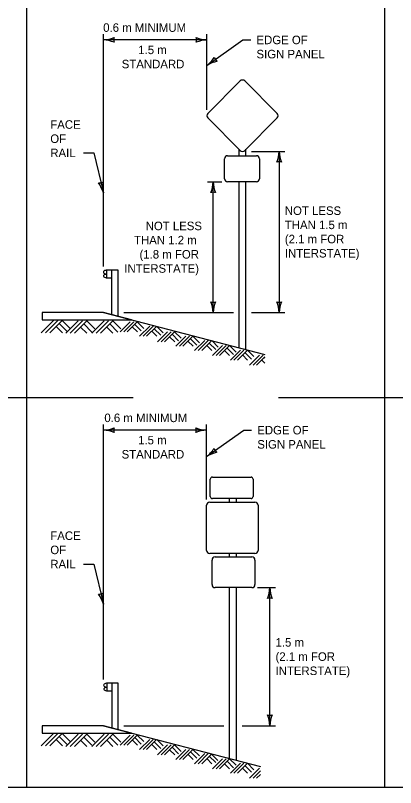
# Model space of a CAD drawing. Extents: x 49991.4 to 50021, y 49987.6 to 50011.4.
# Drawn here: x 50003.15 to 50005.83, y 49987.8 to 49993.24 of the extents above; entities that cross this region are included whole.
import ezdxf

# ---------------------------------------------------------------- set-up
doc = ezdxf.new("R2010")
doc.units = 0
for name, color, linetype in [('Level 1', 7, 'Continuous'), ('Level 2', 7, 'Continuous'), ('Level 3', 7, 'Continuous')]:
    doc.layers.add(name, color=color, linetype=linetype)

msp = doc.modelspace()

# ---------------------------------------------------------------- linework, layer by layer
at = {"layer": 'Level 1'}
for p, q in [((50004.5041, 49992.5484), (50004.7327, 49992.7772)), ((50004.7645, 49992.7772), (50004.9934, 49992.5484)), ((50004.7327, 49992.2877), (50004.5041, 49992.5166)), ((50004.9934, 49992.5166), (50004.7645, 49992.2877)), ((50004.7243, 49992.2506), (50004.7243, 49992.2961)), ((50004.7729, 49992.2506), (50004.7729, 49992.2961)), ((50004.622, 49992.0878), (50004.622, 49992.2291)), ((50004.6435, 49992.2506), (50004.8461, 49992.2506)), ((50004.8676, 49992.2291), (50004.8676, 49992.0878)), ((50004.8461, 49992.0663), (50004.6435, 49992.0663)), ((50004.7243, 49990.8966), (50004.7243, 49992.0663)), ((50004.7729, 49990.884), (50004.7729, 49992.0663)), ((50003.8289, 49991.4443), (50003.7883, 49991.4443)), ((50003.7901, 49991.4443), (50003.7901, 49991.391)), ((50003.8289, 49991.129), (50003.8289, 49991.4443)), ((50003.8718, 49991.4443), (50003.8289, 49991.4443)), ((50003.8718, 49991.1182), (50003.8718, 49991.4443)), ((50003.7883, 49991.391), (50003.8289, 49991.391)), ((50003.768, 49991.1452), (50003.336, 49991.1452)), ((50003.336, 49991.1452), (50003.336, 49991.0935)), ((50003.768, 49991.1452), (50003.336, 49991.1452)), ((50003.336, 49991.1452), (50003.336, 49991.0935)), ((50003.7682, 49991.1452), (50004.9063, 49990.8493)), ((50003.9668, 49991.0936), (50003.7682, 49991.1452)), ((50003.3298, 49991.0029), (50003.4171, 49991.0903)), ((50003.336, 49991.0935), (50003.9668, 49991.0935)), ((50003.336, 49991.0935), (50003.9668, 49991.0935)), ((50003.3605, 49991.0029), (50003.4478, 49991.0903)), ((50003.3909, 49991.0029), (50003.4782, 49991.0903)), ((50003.4782, 49991.0903), (50003.5351, 49991.0335)), ((50003.5026, 49990.9993), (50003.5899, 49991.0866)), ((50003.5333, 49990.9993), (50003.6206, 49991.0866)), ((50003.5637, 49990.9993), (50003.6511, 49991.0866)), ((50003.6511, 49991.0866), (50003.7079, 49991.0299)), ((50003.6861, 49990.9993), (50003.7734, 49991.0866)), ((50003.7168, 49990.9993), (50003.8041, 49991.0866)), ((50003.7472, 49990.9993), (50003.8346, 49991.0866)), ((50003.8346, 49991.0866), (50003.8914, 49991.0299)), ((50003.8863, 49991.0088), (50003.9571, 49991.0795)), ((50003.9112, 49991.0088), (50003.9819, 49991.0795)), ((50003.9358, 49991.0088), (50004.0065, 49991.0795)), ((50003.9665, 49991.0935), (50003.9665, 49991.0935)), ((50003.9668, 49991.0935), (50003.9668, 49991.0936)), ((50004.0065, 49991.0795), (50004.0526, 49991.0335)), ((50003.4351, 49991.047), (50003.4792, 49991.0029)), ((50003.4568, 49991.0687), (50003.5135, 49991.012)), ((50003.6079, 49991.0433), (50003.652, 49990.9993)), ((50003.6295, 49991.065), (50003.6862, 49991.0084)), ((50003.7914, 49991.0433), (50003.8355, 49990.9993)), ((50003.813, 49991.065), (50003.8697, 49991.0084)), ((50003.9716, 49991.0445), (50004.0075, 49991.0088)), ((50003.9891, 49991.0621), (50004.0352, 49991.0162)), ((50004.0238, 49990.9781), (50004.0945, 49991.0488)), ((50004.0486, 49990.9781), (50004.1193, 49991.0488)), ((50004.0732, 49990.9781), (50004.143, 49991.0477)), ((50004.1266, 49991.0314), (50004.1726, 49990.9855)), ((50004.1459, 49991.047), (50004.19, 49991.0028)), ((50004.109, 49991.0137), (50004.1449, 49990.9781)), ((50004.1495, 49990.9398), (50004.2202, 49991.0105)), ((50004.1744, 49990.9398), (50004.2451, 49991.0105)), ((50004.199, 49990.9398), (50004.2697, 49991.0105)), ((50004.2348, 49990.9755), (50004.2706, 49990.9398)), ((50004.2524, 49990.9931), (50004.2983, 49990.9472)), ((50004.2697, 49991.0105), (50004.3158, 49990.9645)), ((50004.2786, 49990.908), (50004.3493, 49990.9788)), ((50004.3036, 49990.908), (50004.3743, 49990.9788)), ((50004.3282, 49990.908), (50004.3989, 49990.9788)), ((50004.3989, 49990.9788), (50004.445, 49990.9327)), ((50004.3639, 49990.9436), (50004.3997, 49990.908)), ((50004.3814, 49990.9613), (50004.4274, 49990.9154)), ((50004.4114, 49990.8775), (50004.4821, 49990.9482)), ((50004.4362, 49990.8775), (50004.5071, 49990.9482)), ((50004.461, 49990.8775), (50004.5305, 49990.947)), ((50004.5142, 49990.9308), (50004.5602, 49990.8851)), ((50004.5338, 49990.9462), (50004.5778, 49990.9024)), ((50004.4967, 49990.9132), (50004.5324, 49990.8775)), ((50004.5369, 49990.8418), (50004.6076, 49990.9126)), ((50004.5619, 49990.8418), (50004.6326, 49990.9126)), ((50004.5864, 49990.8418), (50004.6571, 49990.9126)), ((50004.6222, 49990.8775), (50004.6579, 49990.8418)), ((50004.6396, 49990.8951), (50004.6857, 49990.8492)), ((50004.6571, 49990.9126), (50004.7033, 49990.8665)), ((50004.6631, 49990.8107), (50004.7339, 49990.8814)), ((50004.688, 49990.8107), (50004.7588, 49990.8814)), ((50004.7126, 49990.8107), (50004.7834, 49990.8813)), ((50004.766, 49990.864), (50004.812, 49990.8181)), ((50004.7837, 49990.8812), (50004.8295, 49990.8355)), ((50004.7485, 49990.8464), (50004.7842, 49990.8107)), ((50004.7985, 49990.7748), (50004.8692, 49990.8455)), ((50004.8235, 49990.7748), (50004.8942, 49990.8455)), ((50004.848, 49990.7748), (50004.9063, 49990.833)), ((50004.8839, 49990.8105), (50004.9063, 49990.7882)), ((50004.9013, 49990.8281), (50004.9063, 49990.8231)), ((50004.5214, 49989.8499), (50004.5214, 49989.9711)), ((50004.5364, 49989.9861), (50004.8085, 49989.9861)), ((50004.8235, 49989.9711), (50004.8235, 49989.8499)), ((50004.8085, 49989.8349), (50004.5364, 49989.8349)), ((50004.6569, 49989.8098), (50004.6569, 49989.8349)), ((50004.7055, 49989.8098), (50004.7055, 49989.8349)), ((50004.4955, 49989.4698), (50004.4955, 49989.7873)), ((50004.518, 49989.8098), (50004.8356, 49989.8098)), ((50004.8581, 49989.7873), (50004.8581, 49989.4698)), ((50004.8356, 49989.4473), (50004.518, 49989.4473)), ((50004.6569, 49989.4234), (50004.6569, 49989.4473)), ((50004.7055, 49989.4234), (50004.7055, 49989.4473)), ((50004.5342, 49989.229), (50004.5342, 49989.4019)), ((50004.5557, 49989.4234), (50004.8149, 49989.4234)), ((50004.8364, 49989.4019), (50004.8364, 49989.229)), ((50004.8149, 49989.2075), (50004.5557, 49989.2075)), ((50004.6569, 49988.0034), (50004.6569, 49989.2075)), ((50004.7056, 49987.9907), (50004.7056, 49989.2075)), ((50003.8302, 49988.5334), (50003.7896, 49988.5334)), ((50003.7914, 49988.5334), (50003.7914, 49988.4801)), ((50003.8302, 49988.2183), (50003.8302, 49988.5334)), ((50003.8731, 49988.5334), (50003.8302, 49988.5334)), ((50003.8731, 49988.2072), (50003.8731, 49988.5334)), ((50003.7896, 49988.4801), (50003.8302, 49988.4801)), ((50003.768, 49988.2345), (50003.336, 49988.2345)), ((50003.336, 49988.2345), (50003.336, 49988.1829)), ((50003.768, 49988.2345), (50003.336, 49988.2345)), ((50003.336, 49988.2345), (50003.336, 49988.1829)), ((50003.7682, 49988.2345), (50004.875, 49987.9467)), ((50003.9666, 49988.1829), (50003.7682, 49988.2345)), ((50003.3298, 49988.0923), (50003.4171, 49988.1796)), ((50003.336, 49988.1829), (50003.9667, 49988.1829)), ((50003.336, 49988.1829), (50003.9666, 49988.1829)), ((50003.3605, 49988.0923), (50003.4478, 49988.1796)), ((50003.3909, 49988.0923), (50003.4782, 49988.1796)), ((50003.4568, 49988.158), (50003.5135, 49988.1014)), ((50003.4782, 49988.1796), (50003.5351, 49988.1228)), ((50003.5026, 49988.0886), (50003.5899, 49988.176)), ((50003.5333, 49988.0886), (50003.6206, 49988.176)), ((50003.5637, 49988.0886), (50003.651, 49988.176)), ((50003.6295, 49988.1544), (50003.6862, 49988.0977)), ((50003.651, 49988.176), (50003.7079, 49988.1192)), ((50003.6861, 49988.0886), (50003.7734, 49988.176)), ((50003.7168, 49988.0886), (50003.8041, 49988.176)), ((50003.7472, 49988.0886), (50003.8345, 49988.176)), ((50003.813, 49988.1544), (50003.8697, 49988.0977)), ((50003.8345, 49988.176), (50003.8914, 49988.1192)), ((50003.8863, 49988.0981), (50003.957, 49988.1688)), ((50003.9112, 49988.0981), (50003.9819, 49988.1688)), ((50003.9358, 49988.0981), (50004.0065, 49988.1688)), ((50003.9665, 49988.1829), (50003.9665, 49988.1829)), ((50003.9891, 49988.1515), (50004.0351, 49988.1055)), ((50004.0065, 49988.1688), (50004.0526, 49988.1228)), ((50003.435, 49988.1363), (50003.4792, 49988.0923)), ((50003.6079, 49988.1327), (50003.652, 49988.0886)), ((50003.7914, 49988.1327), (50003.8355, 49988.0886)), ((50003.9716, 49988.1339), (50004.0075, 49988.0981)), ((50004.0237, 49988.0674), (50004.0944, 49988.1381)), ((50004.0486, 49988.0674), (50004.1193, 49988.1381)), ((50004.0732, 49988.0674), (50004.143, 49988.1371)), ((50004.109, 49988.1031), (50004.1449, 49988.0674)), ((50004.1266, 49988.1208), (50004.1725, 49988.0748)), ((50004.1458, 49988.1363), (50004.19, 49988.0922)), ((50004.1495, 49988.0291), (50004.2202, 49988.0998)), ((50004.1744, 49988.0291), (50004.2451, 49988.0998)), ((50004.199, 49988.0291), (50004.2697, 49988.0998)), ((50004.2697, 49988.0998), (50004.3158, 49988.0538)), ((50004.2348, 49988.0649), (50004.2705, 49988.0291)), ((50004.2524, 49988.0825), (50004.2983, 49988.0365)), ((50004.2785, 49987.9973), (50004.3493, 49988.0681)), ((50004.3035, 49987.9973), (50004.3742, 49988.0681)), ((50004.3282, 49987.9973), (50004.3989, 49988.0681)), ((50004.3639, 49988.033), (50004.3997, 49987.9973)), ((50004.3814, 49988.0507), (50004.4274, 49988.0047)), ((50004.3989, 49988.0681), (50004.4449, 49988.0221)), ((50004.4113, 49987.9669), (50004.4821, 49988.0376)), ((50004.4362, 49987.9669), (50004.507, 49988.0376)), ((50004.461, 49987.9669), (50004.5292, 49988.0351)), ((50004.5292, 49988.0351), (50004.5752, 49987.9892)), ((50004.4967, 49988.0025), (50004.5324, 49987.9669)), ((50004.5142, 49988.0201), (50004.5602, 49987.9744)), ((50004.5369, 49987.9311), (50004.6076, 49988.0019)), ((50004.5619, 49987.9311), (50004.6326, 49988.0019)), ((50004.5864, 49987.9311), (50004.6571, 49988.0019)), ((50004.6396, 49987.9845), (50004.6857, 49987.9385)), ((50004.6571, 49988.0019), (50004.7033, 49987.9558)), ((50004.6221, 49987.9669), (50004.6579, 49987.9311)), ((50004.6631, 49987.9), (50004.7338, 49987.9708)), ((50004.688, 49987.9), (50004.7588, 49987.9708)), ((50004.7126, 49987.9), (50004.7832, 49987.9706)), ((50004.7485, 49987.9357), (50004.7842, 49987.9)), ((50004.766, 49987.9533), (50004.8119, 49987.9074)), ((50004.7838, 49987.9704), (50004.8295, 49987.9248)), ((50004.7985, 49987.8641), (50004.8692, 49987.9349)), ((50004.8235, 49987.8641), (50004.875, 49987.9157)), ((50004.848, 49987.8641), (50004.875, 49987.8911))]:
    msp.add_line(p, q, dxfattribs=at)
msp.add_lwpolyline([(49999.3835, 49998.9992), (50016.7501, 49998.9992), (50016.7501, 49987.7988), (49999.3835, 49987.7988)], close=True, dxfattribs=at)
for centre, radius, start, end in [((50004.7486, 49992.7613), 0.0225, 45.011, 135.022), ((50004.52, 49992.5325), 0.0225, 135.022, 224.967), ((50004.9775, 49992.5325), 0.0225, 315, 45.011), ((50004.7486, 49992.3036), 0.0225, 224.967, 315), ((50004.6435, 49992.2291), 0.0215, 90, 180), ((50004.8461, 49992.2291), 0.0215, 0, 90), ((50004.6435, 49992.0878), 0.0215, 180, 270), ((50004.8461, 49992.0878), 0.0215, 270, 0), ((50004.5364, 49989.9711), 0.015, 90, 180), ((50004.8085, 49989.9711), 0.015, 0, 90), ((50004.5364, 49989.8499), 0.015, 180, 270), ((50004.8085, 49989.8499), 0.015, 270, 0), ((50004.518, 49989.7873), 0.0225, 90, 180), ((50004.8356, 49989.7873), 0.0225, 0, 90), ((50004.518, 49989.4698), 0.0225, 180, 270), ((50004.8356, 49989.4698), 0.0225, 270, 0), ((50004.5557, 49989.4019), 0.0215, 90, 180), ((50004.8149, 49989.4019), 0.0215, 0, 90), ((50004.5557, 49989.229), 0.0215, 180, 270), ((50004.8149, 49989.229), 0.0215, 270, 0)]:
    msp.add_arc(centre, radius, start, end, dxfattribs=at)
for points in [[(50003.7883, 49991.4443), (50003.7696, 49991.4337), (50003.7692, 49991.4267), (50003.7883, 49991.4176), (50003.789, 49991.4174), (50003.7692, 49991.4062), (50003.7696, 49991.4025), (50003.7883, 49991.391)], [(50003.7896, 49988.5334), (50003.7709, 49988.5228), (50003.7705, 49988.5158), (50003.7896, 49988.5067), (50003.7903, 49988.5065), (50003.7705, 49988.4953), (50003.7709, 49988.4916), (50003.7896, 49988.4801)]]:
    msp.add_spline(points, degree=3, dxfattribs=at)
at = {"layer": 'Level 3'}
for p, q in [((50003.2287, 49987.7988), (50003.2287, 49998.9992)), ((50005.7525, 49987.7988), (50005.7525, 49998.9992)), ((50003.768, 49991.4699), (50003.768, 49993.1063)), ((50004.4975, 49992.5725), (50004.4975, 49993.1063)), ((50004.4975, 49993.0663), (50003.768, 49993.0663)), ((50004.4975, 49992.8854), (50004.7515, 49993.0663)), ((50004.7515, 49993.0663), (50004.8069, 49993.0663)), ((50004.8129, 49992.2811), (50005.0467, 49992.2811)), ((50005.0067, 49992.2811), (50005.0067, 49991.1452)), ((50003.6292, 49992.2702), (50003.7012, 49992.2702)), ((50003.7012, 49992.2702), (50003.768, 49991.9887)), ((50004.502, 49992.0663), (50004.6035, 49992.0663)), ((50004.542, 49991.1452), (50004.542, 49992.0663)), ((50003.9118, 49991.1452), (50004.6843, 49991.1452)), ((50004.8129, 49991.1452), (50005.0467, 49991.1452)), ((50002.4787, 49990.5461), (50003.9787, 49990.5461)), ((50005.0025, 49990.5461), (50006.5025, 49990.5461)), ((50003.768, 49988.5594), (50003.768, 49990.3568)), ((50004.4955, 49990.3168), (50003.768, 49990.3168)), ((50004.4955, 49989.8273), (50004.4955, 49990.3568)), ((50004.4955, 49990.1305), (50004.7572, 49990.3168)), ((50004.7572, 49990.3168), (50004.8126, 49990.3168)), ((50003.6292, 49989.3733), (50003.7012, 49989.3733)), ((50003.7012, 49989.3733), (50003.768, 49989.0918)), ((50004.8549, 49989.2075), (50004.9812, 49989.2075)), ((50004.9412, 49988.2345), (50004.9412, 49989.2075)), ((50003.9131, 49988.2345), (50004.6169, 49988.2345)), ((50004.7456, 49988.2345), (50004.9812, 49988.2345))]:
    msp.add_line(p, q, dxfattribs=at)
for centre, radius, start, end in [((50003.7565, 49993.299), 0.233, 272.8273, 292.0772), ((50003.7588, 49992.8442), 0.2223, 67.456, 87.6395), ((50003.8962, 49993.0663), 0.0548, 162.1388, 197.8612), ((50004.5067, 49993.2884), 0.2223, 247.456, 267.6395), ((50004.3693, 49993.0663), 0.0548, 342.1388, 17.8612), ((50004.509, 49992.8336), 0.233, 92.8273, 112.0772), ((50004.3531, 49993.0683), 0.233, 308.286, 327.5358), ((50004.6019, 49992.9598), 0.0548, 197.5975, 233.3198), ((50004.6189, 49992.6992), 0.2223, 102.9147, 123.0982), ((50004.7846, 49992.2903), 0.2223, 337.456, 357.6395), ((50005.2394, 49992.2926), 0.233, 182.8273, 202.0772), ((50005.0067, 49992.1529), 0.0548, 72.1388, 107.8612), ((50003.7376, 49992.1133), 0.0548, 265.8498, 301.5721), ((50003.5446, 49991.9224), 0.233, 16.5382, 35.7881), ((50003.986, 49992.0325), 0.2223, 171.1669, 191.3505), ((50004.3199, 49992.0755), 0.2223, 337.456, 357.6395), ((50004.7747, 49992.0778), 0.233, 182.8273, 202.0772), ((50004.542, 49991.9381), 0.0548, 72.1388, 107.8612), ((50004.542, 49991.2734), 0.0548, 252.1388, 287.8612), ((50004.3093, 49991.1337), 0.233, 2.8273, 22.0772), ((50004.7641, 49991.136), 0.2223, 157.456, 177.6395), ((50005.0067, 49991.2734), 0.0548, 252.1388, 287.8612), ((50004.774, 49991.1337), 0.233, 2.8273, 22.0772), ((50005.2288, 49991.136), 0.2223, 157.456, 177.6395), ((50003.7565, 49990.5495), 0.233, 272.8273, 292.0772), ((50003.7588, 49990.0947), 0.2223, 67.456, 87.6395), ((50003.8962, 49990.3168), 0.0548, 162.1388, 197.8612), ((50004.5047, 49990.5389), 0.2223, 247.456, 267.6395), ((50004.3673, 49990.3168), 0.0548, 342.1388, 17.8612), ((50004.507, 49990.0841), 0.233, 92.8273, 112.0772), ((50004.3512, 49990.3134), 0.233, 308.2738, 327.5236), ((50004.6169, 49989.9442), 0.2223, 102.9025, 123.086), ((50004.6, 49990.2049), 0.0548, 197.5853, 233.3076), ((50004.7191, 49989.2167), 0.2223, 337.456, 357.6395), ((50005.1739, 49989.219), 0.233, 182.8273, 202.0772), ((50003.7376, 49989.2164), 0.0548, 265.8498, 301.5721), ((50003.5446, 49989.0255), 0.233, 16.5382, 35.7881), ((50003.986, 49989.1356), 0.2223, 171.1669, 191.3505), ((50004.9412, 49989.0793), 0.0548, 72.1388, 107.8612), ((50004.9412, 49988.3627), 0.0548, 252.1388, 287.8612), ((50004.7085, 49988.223), 0.233, 2.8273, 22.0772), ((50005.1633, 49988.2253), 0.2223, 157.456, 177.6395)]:
    msp.add_arc(centre, radius, start, end, dxfattribs=at)

# ---------------------------------------------------------------- texts
at = {"layer": 'Level 2'}
for s, p in [('0.6 m MINIMUM', (50003.767, 49993.1231)), ('EDGE OF', (50004.8469, 49993.0363)), ('1.5 m', (50004.0141, 49992.9663)), ('SIGN PANEL', (50004.8469, 49992.9363)), ('STANDARD', (50003.8976, 49992.8663)), ('FACE', (50003.3941, 49992.4402)), ('OF', (50003.3941, 49992.3402)), ('RAIL', (50003.3941, 49992.2402)), ('NOT LESS', (50005.0467, 49991.8332)), ('NOT LESS', (50004.0663, 49991.7258)), ('THAN 1.5 m', (50005.0467, 49991.7332)), ('THAN 1.2 m', (50003.9843, 49991.6258)), ('(2.1 m FOR', (50005.0467, 49991.6332)), ('(1.8 m FOR', (50004.0227, 49991.5258)), ('INTERSTATE)', (50005.0467, 49991.5332)), ('INTERSTATE)', (50003.9159, 49991.4258)), ('0.6 m MINIMUM', (50003.7751, 49990.3736)), ('EDGE OF', (50004.8526, 49990.2868)), ('1.5 m', (50004.0131, 49990.2168)), ('SIGN PANEL', (50004.8526, 49990.1868)), ('STANDARD', (50003.8966, 49990.1168)), ('FACE', (50003.3941, 49989.5433)), ('OF', (50003.3941, 49989.4433)), ('RAIL', (50003.3941, 49989.3433)), ('1.5 m', (50004.9812, 49988.7916)), ('(2.1 m FOR', (50004.9812, 49988.6916)), ('INTERSTATE)', (50004.9812, 49988.5916))]:
    msp.add_text(s, height=0.06, dxfattribs=at).set_placement(p)

doc.saveas('drawing.dxf')
